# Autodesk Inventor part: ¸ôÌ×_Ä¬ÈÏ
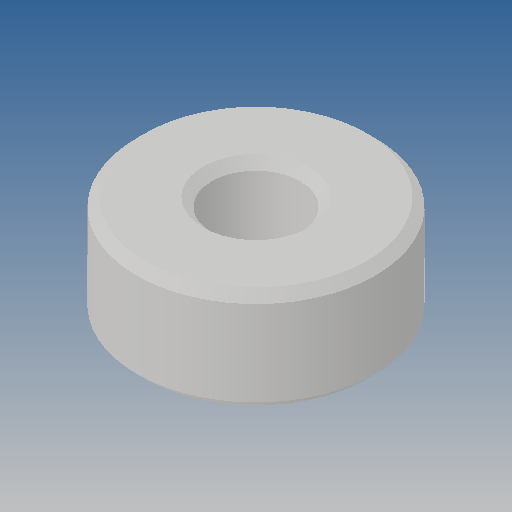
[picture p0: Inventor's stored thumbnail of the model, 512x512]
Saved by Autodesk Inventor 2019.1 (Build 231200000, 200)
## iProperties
Created: 2012-10
Part Number: ¸ôÌ×_Ä¬ÈÏ
Material: Ogólny
Document SubType Name: Modeling
Designer: CADENGINEERING4
Density: 1 g/cm^3
Appearance: Domyślna
Author: CADENGINEERING4
Revision Number: ÈÎºÎ
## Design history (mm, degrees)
feature "NONE"
node "Bryła1"
